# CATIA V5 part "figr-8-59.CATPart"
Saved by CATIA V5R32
Part number: Part1
Bounding box of the stored display mesh (mm): x -50.499 to 50.499, y -68.48 to 68.48, z -50 to 50
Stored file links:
  D:\PROJECTS\Project 2022\CATIA V5 6R 2022\Resources\Part Files\c08_catia_v5_6r2022_prt\figr-8-59.CATPart
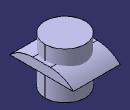
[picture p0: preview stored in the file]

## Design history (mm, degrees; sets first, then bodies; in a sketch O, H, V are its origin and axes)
Body1 (main body)
  Sketch1 on xy-plane, origin (0, 0, 0), H (1, 0, 0), V (0, 1, 0)
    line L1 (-50.499, 68.4797) -> (50.499, 68.4797)
    line L2 (50.499, 68.4797) -> (50.499, -68.4797)
    line L3 (50.499, -68.4797) -> (-50.499, -68.4797)
    line L4 (-50.499, -68.4797) -> (-50.499, 68.4797)
    axis line L5 (50.499, -68.4797) -> (-50.499, 68.4797)
    horizontal: L1 H, L3 H
    vertical: L2 V, L4 V
    midpoint: O L5
  Pad1: profile Sketch1, direction (0, 0, 1), length 20
  Fillet1: radius 71, on edge [face of Pad1 | face of Pad1]
  Fillet2: radius 71, on edge [face of Pad1 | face of Pad1]
Body2
  Sketch2 on xy-plane, origin (0, 0, 0), H (1, 0, 0), V (0, 1, 0)
    circle A1 centre (0, 0) radius 43.2524
    point P1 (0, 43.2524)
    coincidence: A1 P1, P1 V
  Pocket1: profile Sketch2, direction (0, 0, -1), length 50, mirrored extent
